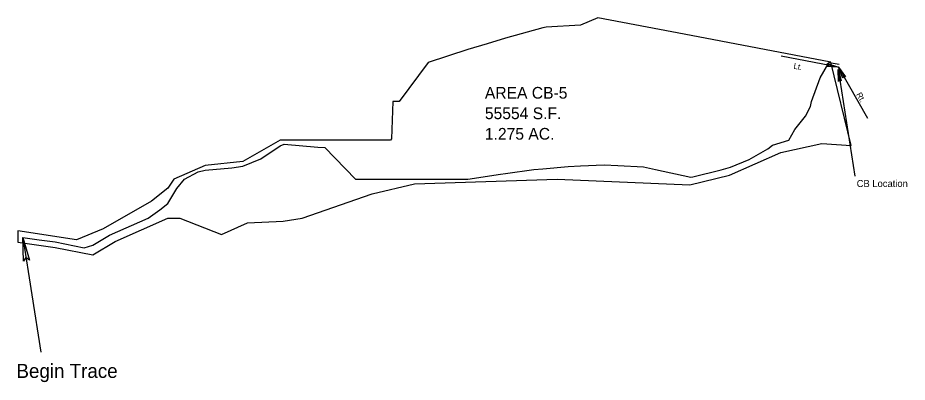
# Model space of a CAD drawing. Extents: x 2238 to 2999, y 2892 to 3203.
import ezdxf

# ---------------------------------------------------------------- set-up
doc = ezdxf.new("R2010")
doc.units = 0
for name, color, linetype in [('Default', 7, 'Continuous'), ('DESIGN - SCRATCH - User 1', 7, 'Continuous'), ('SURVEY - CENTERLINE - Preliminary', 7, 'Continuous'), ('SURVEY - CENTERLINE - Preliminary Text', 7, 'Continuous'), ('SURVEY - CONTROL with Text', 7, 'Continuous'), ('SURVEY - DRAINAGE - Area Shapes', 7, 'Continuous')]:
    doc.layers.add(name, color=color, linetype=linetype)

msp = doc.modelspace()

# ---------------------------------------------------------------- linework, layer by layer
at = {"layer": 'DESIGN - SCRATCH - User 1'}
msp.add_line((2939.51, 3158.67), (2953.97, 3067.68), dxfattribs=at)
msp.add_lwpolyline([(2939.51, 3158.67), (2942.32, 3148.94), (2940.88, 3150.03), (2939.8, 3148.54)], close=True, dxfattribs=at)
msp.add_lwpolyline([(2939.51, 3158.67), (2942.32, 3148.94), (2940.88, 3150.03), (2939.8, 3148.54), (2939.51, 3158.67)], dxfattribs=at)
at = {"layer": 'SURVEY - CENTERLINE - Preliminary'}
msp.add_lwpolyline([(2242.25, 3015.31), (2256.15, 3013.11), (2270.08, 3011.64), (2294.74, 3006.37), (2302.16, 3008.6), (2316.39, 3017.16), (2349.54, 3031.88), (2359.59, 3038.83), (2366.31, 3044.28), (2374.09, 3057.02), (2380.62, 3065.07), (2392.39, 3071.27), (2398.39, 3072.86), (2421.18, 3074.67), (2430.47, 3076.01), (2445.79, 3082.4), (2462.54, 3093.37), (2465.89, 3094.79), (2494.62, 3092.35), (2500.72, 3091.95), (2526.7, 3065.07), (2558.77, 3065.07), (2590.85, 3065.07), (2622.93, 3065.07), (2650.83, 3069.39), (2655.01, 3069.96), (2679.25, 3073.17), (2687.08, 3073.97), (2708.64, 3075.96), (2719.16, 3076.46), (2739.46, 3077.25), (2751.24, 3076.63), (2773.22, 3075.51), (2783.31, 3073.42), (2813.75, 3066.77), (2815.39, 3067.17), (2839.68, 3073.13), (2847.47, 3075.36), (2863.47, 3081.7), (2879.54, 3090.89), (2883.55, 3094.11), (2897.47, 3098.26), (2902.69, 3107.5), (2911.62, 3118.71), (2915.82, 3127.1), (2916.81, 3131.44), (2924.17, 3151.65), (2931.7, 3164.28), (2931.82, 3164.58), (2931.82, 3164.58), (2931.82, 3164.59), (2931.83, 3164.64), (2935.45, 3164.07), (2940.4, 3163.31)], dxfattribs=at)
at = {"layer": 'SURVEY - CENTERLINE - Preliminary Text'}
msp.add_line((2242.25, 3015.31), (2257.83, 2917.29), dxfattribs=at)
msp.add_lwpolyline([(2242.25, 3015.31), (2247.88, 2995.85), (2245, 2998.02), (2242.84, 2995.05)], close=True, dxfattribs=at)
msp.add_lwpolyline([(2242.25, 3015.31), (2247.88, 2995.85), (2245, 2998.02), (2242.84, 2995.05), (2242.25, 3015.31)], dxfattribs=at)
at = {"layer": 'SURVEY - CONTROL with Text'}
for q in [(2890.77, 3170.03), (2964.63, 3117.19)]:
    msp.add_line((2939.88, 3160.63), q, dxfattribs=at)
for points in [[(2939.88, 3160.63), (2929.78, 3161.29), (2931.29, 3162.28), (2930.26, 3163.8)], [(2939.88, 3160.63), (2945.94, 3152.52), (2944.21, 3153.03), (2943.73, 3151.26)]]:
    msp.add_lwpolyline(points, close=True, dxfattribs=at)
for points in [[(2939.88, 3160.63), (2929.78, 3161.29), (2931.29, 3162.28), (2930.26, 3163.8), (2939.88, 3160.63)], [(2939.88, 3160.63), (2945.94, 3152.52), (2944.21, 3153.03), (2943.73, 3151.26), (2939.88, 3160.63)]]:
    msp.add_lwpolyline(points, dxfattribs=at)
at = {"layer": 'SURVEY - DRAINAGE - Area Shapes'}
for p, q in [((2933.36, 3164.93), (2807.85, 3188.95)), ((2950.76, 3093.65), (2933.36, 3164.93))]:
    msp.add_line(p, q, dxfattribs=at)
for points in [[(2807.85, 3188.95), (2734.14, 3202.79), (2719.16, 3196.62), (2689.87, 3194.93), (2687.08, 3194.37), (2655.01, 3185.45)], [(2655.01, 3185.45), (2639.57, 3180.6), (2622.93, 3175.83), (2589.08, 3164.63), (2564.25, 3131.44), (2558.77, 3131.44), (2557.54, 3099.53), (2556.8, 3098.26), (2529.54, 3098.26)], [(2529.54, 3098.26), (2462.54, 3098.26), (2430.47, 3080.21), (2398.39, 3076.83), (2371.56, 3065.07), (2366.31, 3057.45), (2352.46, 3046.21), (2311.04, 3022.69), (2288.19, 3013.15), (2238, 3021.05)], [(2541.16, 3052.53), (2577.34, 3061.02), (2699.28, 3065.04), (2812.74, 3060.13), (2846.75, 3068.32), (2890.46, 3087.84), (2925.75, 3095.43), (2950.76, 3093.65)], [(2238, 3021.05), (2238, 3011.2), (2270.08, 3006.58), (2302.16, 3000.37), (2321.42, 3011.95), (2366.31, 3031.88), (2376.54, 3031.88), (2412.09, 3017.7), (2434.51, 3027.7), (2465.1, 3029.23), (2481.15, 3031.88), (2541.16, 3052.53)]]:
    msp.add_lwpolyline(points, dxfattribs=at)

# ---------------------------------------------------------------- texts
at = {"layer": 'Default'}
for s, p in [('AREA CB-5', (2637.48, 3133.77)), ('55554 S.F.', (2637.48, 3116.27)), ('1.275 AC.', (2637.48, 3098.77))]:
    msp.add_text(s, height=10, dxfattribs=at).set_placement(p)
at = {"layer": 'DESIGN - SCRATCH - User 1'}
msp.add_text('CB Location', height=6, dxfattribs=at).set_placement((2955.48, 3058.33))
at = {"layer": 'SURVEY - CENTERLINE - Preliminary Text'}
msp.add_text('Begin Trace ', height=12, dxfattribs=at).set_placement((2236.87, 2895.33))
at = {"layer": 'SURVEY - CONTROL with Text'}
for s, rotation, p in [('Lt.', 349.16668, (2901.14, 3159.39)), ('Rt.', 299.66576, (2954.85, 3137.38))]:
    msp.add_text(s, height=5, rotation=rotation, dxfattribs=at).set_placement(p)

doc.saveas('drawing.dxf')
